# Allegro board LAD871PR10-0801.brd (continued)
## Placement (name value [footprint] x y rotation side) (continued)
PU1200  -  [NB681GD-Z_QFN13_2X3]  36.32 53.21 0 bottom
PU1400  SY8286RAC_QFN20_3X3  [SY8286RAC_QFN20_3X3-S]  130.93 138.81 180 bottom
PWR1  JXT_FP202DH-004M10M  [JXT_FP202DH-004M10M_4P]  197.15 167.84 0 top
Q1901  -  [2N7002K_SOT23-3]  165.5 64.77 90 top
Q2405  -  [2N7002K_SOT23-3]  53.55 72.64 90 top
Q2505  -  [2N7002K_SOT23-3]  31.27 16.76 270 top
Q2601  -  [DMN66D0LDW-7_SOT363-6]  153.49 156.78 180 bottom
Q2603  -  [LMBT3904LT1G_SOT23-3]  53.02 64.11 180 bottom
Q3001  -  [2N7002K_SOT23-3]  61.93 169.55 180 top
Q3004  NTK3139PT1G_SOT723-3  [2N7002K_SOT23-3]  57.56 171.84 270 top
Q5401  LMBT3904LT1G-GP  [MMBT3904_SOT23-3]  27.59 78.99 270 top
Q5402  -  [DMN66D0LDW-7_SOT363-6]  33 78.25 90 bottom
Q5403  -  [2N7002K_SOT23-3]  28.99 73.98 270 top
Q6101  -  [DDTA144VCA-7-F_SOT23-3]  35.24 5.25 0 top
Q6102  -  [DDTA144VCA-7-F_SOT23-3]  31.3 5.82 0 top
Q6105  -  [2N7002K_SOT23-3]  44.27 12.37 180 top
Q6201  -  [DDTA144VCA-7-F_SOT23-3]  195.51 108.94 0 top
Q6202  -  [LN2306LT1G_SOT23-3]  188.42 126.68 90 top
Q6203  NTK3139PT1G_SOT723-3  [2N7002K_SOT23-3]  52.13 79.02 180 top
Q6204  -  [LN2306LT1G_SOT23-3]  55.4 70.48 270 top
Q6205  -  [LN2306LT1G_SOT23-3]  196.53 18.01 180 bottom
Q6206  -  [LN2306LT1G_SOT23-3]  195.64 106.45 180 top
Q6501  -  [DMN66D0LDW-7_SOT363-6]  45.44 72.8 0 top
QC2  -  [DMN66D0LDW-7_SOT363-6]  155.17 91.37 0 bottom
QC4  -  [DMN66D0LDW-7_SOT363-6]  35.76 11.36 180 top
QV1  DMN66D0LDW-7 2N SOT363-6  [2N7002KDWH_SOT363-6]  174.05 125.35 135 top
R437  4.7K_0402_5%  [R_0402]  141.09 159.52 270 top
R1902  10K_0402_5%  [R_0402]  163.52 67.31 180 top
R2405  0_0402_5%  [R_0402]  195.76 85.48 270 top
R2407  100K_0402_1%  [R_0402]  182.62 61.85 180 top
R2446  10K_0402_1%  [R_0402]  182.62 60.96 180 top
R2455  0_0402_5%  [R_0402]  181.79 85.93 270 top
R2502  1K_0402_5%  [R_0402]  32.52 14.35 180 top
R2504  10M_0402_5%  [R_0402]  33.38 14.35 0 top
R2603  18.7K_0402_1%  [R_0402]  159.82 158.62 90 bottom
R2604  2K_0402_1%  [R_0402]  158.24 167.72 270 bottom
R2605  0_0402_5%  [R_0402]  95.19 143.73 0 bottom
R2606  0_0402_5%  [R0402_0OHM]  96.93 140.17 180 bottom
R2608  6.98K_0402_1%  [R_0402]  121.9 99.86 270 bottom
R2609  24.9K_0402_1%  [R_0402]  122.79 99.86 270 bottom
R2610  100K +-1% NCP15WF104F03RC 0402  [R_0402]  121.79 94.49 0 top
R2611  0_0402_5%  [R0402_0OHM]  187.25 73.29 270 bottom
R2701  0_0402_5%  [R0402_0OHM]  177.27 20.45 0 top
R2702  0_0805_5%  [R0805_0OHM]  176.2 10.83 0 bottom
R2703  0_0603_5%  [R0603_0OHM]  192.65 19.69 0 bottom
R2704  0_0805_5%  [R0805_0OHM]  176.2 9.11 0 bottom
R2705  0_0402_5%  [R0402_0OHM]  189.11 7.56 180 bottom
R2706  0_0805_5%  [R0805_0OHM]  191.99 10.54 0 bottom
R2707  20K_0402_1%  [R_0402]  181.94 21.67 90 bottom
R2708  0_0402_5%  [R0402_0OHM]  177.4 13.21 0 top
R2709  200K_0402_1%  [R_0402]  180.8 21.67 90 bottom
R2711  100K_0402_5%  [R_0402]  190.15 19.52 180 bottom
R2712  0_0402_5%  [R0402_0OHM]  186.87 29.13 90 bottom
R2713  0_0402_5%  [R_0402]  185.92 29.13 90 bottom
R2714  0_0402_5%  [R0402_0OHM]  177.29 13.3 0 bottom
R2716  BLM15PX221SN1D_2P  [MURAT_BLM15PX221SN1D_2P]  177.29 14.19 0 bottom
R2717  10K_0402_5%  [R_0402]  178.24 25.45 90 bottom
R2718  33_0402_5%  [R_0402]  177.35 18.8 0 bottom
R2719  0_0402_5%  [R0402_0OHM]  177.1 15.52 0 bottom
R2720  0_0402_5%  [R0402_0OHM]  177.23 16.41 0 bottom
R2722  100K_0402_5%  [R_0402]  178.42 22.48 0 bottom
R2901  BLM15PD800SN1D_2P  [MURAT_BLM15PD800SN1D_2P]  90.56 5.08 0 top
R2902  BLM15PD800SN1D_2P  [MURAT_BLM15PD800SN1D_2P]  90.56 6.67 0 top
R2903  BLM15PD800SN1D_2P  [MURAT_BLM15PD800SN1D_2P]  90.56 8.64 0 top
R2904  BLM15PD800SN1D_2P  [MURAT_BLM15PD800SN1D_2P]  90.56 9.97 0 top
R2906  0_0603_5%  [R0603_0OHM]  185.37 22.13 180 top
R2907  0_0603_5%  [R0603_0OHM]  185.37 28.1 180 top
R2908  10_0402_1%  [R_0402]  188.85 15.27 0 bottom
R2909  0_0603_5%  [R0603_0OHM]  185.37 26.7 180 top
R2910  10_0402_1%  [R_0402]  191.88 15.75 0 bottom
R2911  0_0603_5%  [R0603_0OHM]  185.37 23.53 180 top
R2912  4.7K_0402_5%  [R_0402]  189.74 16.16 0 bottom
R2913  4.7K_0402_5%  [R_0402]  191.88 17.4 0 bottom
R2919  10K_0402_5%  [R_0402]  186.49 27.99 90 top
R2920  10K_0402_5%  [R_0402]  186.49 26.87 270 top
R2921  1K_0402_5%  [R_0402]  191.12 24.38 0 bottom
R2922  1K_0402_5%  [R_0402]  191.12 23.11 0 bottom
R2923  0_0603_5%  [R0603_0OHM]  180.8 24.92 270 bottom
R3001  0_0603_5%  [R_0603]  54.56 174.21 90 top
R3005  0_0402_5%  [R0402_0OHM]  53.14 162.05 0 top
R3006  0_0603_5%  [R0603_0OHM]  55.77 172.94 180 top
R3015  15K_0402_5%  [R_0402]  53.91 167.61 0 top
R3016  0_0402_5%  [R0402_0OHM]  56.72 163.88 270 top
R3021  10K_0402_5%  [R_0402]  62.43 173.33 270 top
R3022  20K_0402_5%  [R_0402]  62.38 171.48 180 top
R3023  100K_0402_5%  [R_0402]  63.39 170.45 90 top
R3032  2.49K_0402_1%  [R_0402]  44.43 173.42 0 top
R3101  75_0603_5%  [R_0603]  16.31 169.67 270 top
R3102  75_0603_5%  [R_0603]  16.31 169.67 270 bottom
R3103  75_0603_5%  [R_0603]  16.31 171.07 90 bottom
R3104  75_0603_5%  [R_0603]  16.31 171.07 90 top
R3201  33_0402_5%  [R_0402]  20.68 17.91 90 bottom
R3202  0_0402_5%  [R0402_0OHM]  15.3 21.29 270 bottom
R3203  6.2K_0402_1%  [R_0402]  14.37 12.93 270 bottom
R3204  0_0402_5%  [R_0402]  12.44 11.57 90 bottom
R3205  0_0402_5%  [R_0402]  11.55 11.57 90 bottom
R3301  0_0402_5%  [R0402_0OHM]  30.1 23.08 180 top
R3501  0_0402_5%  [R0402_0OHM]  134.67 98.99 45 bottom
R5201  0_0402_5%  [R0402_0OHM]  93.53 160.91 270 bottom
R5202  100K_0402_5%  [R_0402]  82.35 154.1 180 bottom
R5203  0_0402_5%  [R_0402]  99.04 158.67 270 bottom
R5204  0_0402_5%  [R_0402]  99.93 158.67 270 bottom
R5205  33_0402_5%  [R_0402]  100.86 158.55 270 bottom
R5206  0_0402_5%  [R0402_0OHM]  65.33 164.67 270 top
R5207  33_0402_5%  [R_0402]  94.04 158.11 90 bottom
R5208  10K_0402_5%  [R_0402]  104.63 171.2 0 bottom
R5209  0_0402_5%  [R_0402]  105.54 172.08 180 bottom
R5210  100_0402_5%  [R_0402]  104.63 170.31 0 bottom
R5211  0_0805_5%  [R_0805]  80.32 157.57 270 bottom
R5212  0_0402_5%  [R_0402]  100.86 162.11 270 bottom
R5213  0_0402_5%  [R0402_0OHM]  84.44 159.77 0 bottom
R5214  0_0805_5%  [R_0805]  74.64 164.97 0 bottom
R5218  100K_0402_5%  [R_0402]  87.22 159.68 180 bottom
R5219  100K_0402_5%  [R_0402]  88.09 159.68 0 bottom
R5222  0_0402_5%  [R_0402]  64.45 164.67 270 top
R5229  0_0603_5%  [R_0603]  97.99 155.8 90 bottom
R5230  0_0603_5%  [R0603_0OHM]  89.15 151.26 0 bottom
R5231  0_0603_5%  [R_0603]  89.15 152.53 0 bottom
R5232  0_0603_5%  [R_0603]  95.5 150.69 180 bottom
R5401  5.6_0402_1%  [R_0402]  21.34 77.86 180 bottom
R5402  5.6_0402_1%  [R_0402]  21.34 76.97 180 bottom
R5403  5.6_0402_1%  [R_0402]  21.48 75.89 180 bottom
R5404  5.6_0402_1%  [R_0402]  21.48 75 180 bottom
R5405  5.6_0402_1%  [R_0402]  20.45 68.9 270 bottom
R5406  5.6_0402_1%  [R_0402]  21.34 68.9 270 bottom
R5407  5.6_0402_1%  [R_0402]  21.46 73.97 180 bottom
R5408  5.6_0402_1%  [R_0402]  21.46 73.08 180 bottom
R5410  200K_0402_1%  [R_0402]  17.1 79.14 90 bottom
R5411  150K_0402_5%  [R_0402]  17.97 79.15 0 bottom
R5412  10K_0402_5%  [R_0402]  31.49 79.36 90 top
R5413  100K_0402_5%  [R_0402]  34.48 70.45 0 bottom
R5414  150_0402_5%  [R_0402]  18.94 77.89 270 bottom
R5415  150_0402_5%  [R_0402]  20.39 66.39 0 bottom
R5416  150_0402_5%  [R_0402]  18.94 75.93 270 bottom
R5417  150_0402_5%  [R_0402]  18.94 73.96 270 bottom
R5418  0_0402_5%  [R_0402]  27.17 74.56 270 top
R5419  0_0402_5%  [R_0402]  31.49 77.52 90 top
R5501  75_0402_1%  [R_0402]  24.08 64.37 270 top
R5502  4.7K_0402_5%  [R_0402]  28.72 59.54 270 bottom
R5503  0_0603_5%  [R0603_0OHM]  23.13 67.4 0 top
R5504  0_0603_5%  [R0603_0OHM]  30.3 59.02 0 top
R5505  12K_0402_1%  [R_0402]  31.7 64.28 90 bottom
R5507  33_0402_5%  [R_0402]  26.81 68.41 90 top
R5508  4.7K_0402_5%  [R_0402]  29.99 61.76 270 bottom
R5509  4.7K_0402_5%  [R_0402]  29.99 59.54 270 bottom
R5510  100K_0402_5%  [R_0402]  31.51 68.09 90 top
R5511  33_0402_5%  [R_0402]  25.92 68.41 90 top
R5512  4.7K_0402_5%  [R_0402]  29.1 61.76 270 bottom
R5513  75_0402_1%  [R_0402]  24.08 62.08 270 top
R5514  75_0402_1%  [R_0402]  24.08 59.42 270 top
R5515  4.7K_0402_5%  [R_0402]  30.88 59.54 270 bottom
R5516  4.7K_0402_5%  [R_0402]  30.88 61.76 270 bottom
R5517  0_0402_5%  [R_0402]  32.4 68.09 90 top
R5601  0_0805_5%  [R0805_0OHM]  192.04 39.81 270 bottom
R5602  0_0402_5%  [R_0402]  153.8 82.36 180 top
R5603  0_0805_5%  [R_0805]  176.14 43.21 270 top
R5604  10K_0402_5%  [R_0402]  152.79 80.39 180 top
R5605  0_0402_5%  [R0402_0OHM]  186.62 35.81 180 bottom
R5607  100K_0402_5%  [R_0402]  181.59 44.45 0 top
R5801  0_0402_5%  [R_0402]  160.47 63.11 90 bottom
R5802  0_0402_5%  [R_0402]  161.36 63.11 90 bottom
R5803  0_0402_5%  [R0402_0OHM]  160.79 49.28 180 bottom
R5804  0_0402_5%  [R_0402]  170.41 49.72 0 top
R5805  0_0402_5%  [R0402_0OHM]  168.4 51.7 270 top
R5806  0_0402_5%  [R_0402]  170.29 52.2 0 top
R5807  0_0402_5%  [R0402_0OHM]  170.41 50.8 0 top
R5808  0_0402_5%  [R0402_0OHM]  159.06 55.42 90 bottom
R5809  0_0805_5%  [R0805_0OHM]  163.7 36.36 90 bottom
R5810  0_0402_5%  [R_0402]  172.71 40.25 90 bottom
R5811  0_0402_5%  [R0402_0OHM]  159.95 55.42 90 bottom
R5812  0_0402_5%  [R0402_0OHM]  170.29 53.21 0 top
R6102  100_0402_5%  [R_0402]  191.12 173.23 0 top
R6103  470R2J-2-GP  [R_0402]  30.99 3.78 0 top
R6107  390R2J-3-GP  [R_0402]  27.87 5.79 270 top
R6109  100_0402_5%  [R_0402]  191.91 175.98 90 top
R6110  10K_0402_5%  [R_0402]  40.9 10.32 0 top
R6201  1K_0402_5%  [R_0402]  195.33 113.03 180 top
R6202  100K_0402_5%  [R_0402]  194.16 100.9 0 top
R6203  10K_0402_5%  [R_0402]  60.71 74.8 180 top
R6206  51K_0402_5%  [R_0402]  186.96 123.21 90 top
R6207  100K_0402_5%  [R_0402]  186.07 123.21 90 top
R6209  4.7K_0402_5%  [R_0402]  59.75 72.09 270 top
R6211  100_0603_1%  [R_0603]  55.49 73.53 0 top
R6212  0_0603_5%  [R_0603]  56.13 78.87 180 top
R6215  0_0402_5%  [R_0402]  54.6 75.17 90 top
R6301  0_0402_5%  [R_0402]  187.56 36.45 0 top
R6302  0_0402_5%  [R_0402]  187.77 31.08 0 top
R6305  0_0603_5%  [R_0603]  192.14 12.06 0 bottom
R6505  100K_0402_5%  [R_0402]  59.8 77.47 0 top
R6506  2.2K_0402_5%  [R_0402]  59.8 73.91 0 top
R6507  10K_0402_5%  [R_0402]  82.66 159.77 0 bottom
R6508  2.2K_0402_5%  [R_0402]  59.8 73.02 0 top
R6510  4.7K_0402_5%  [R_0402]  144.01 159.52 270 top
R6511  0_0402_5%  [R0402_0OHM]  188.33 9 90 bottom
R6512  100K_0402_5%  [R_0402]  177.4 14.1 0 top
R6514  0_0402_5%  [R_0402]  177.48 20.88 90 bottom
R6515  0_0402_5%  [R0402_0OHM]  177.35 19.94 0 bottom
R6516  0_0402_5%  [R0402_0OHM]  179.33 22.61 180 top
R6517  100K_0402_5%  [R_0402]  173.08 53.21 0 top
R6518  1K_0402_5%  [R_0402]  54.83 168.5 180 top
R6519  20K_0402_1%  [R_0402]  48.37 78.49 0 top
R6520  0_0402_5%  [R_0402]  191.95 65.4 0 top
R6522  33_0402_5%  [R_0402]  29.25 19.43 0 top
R6523  0_0402_5%  [R_0402]  187.38 60.12 90 top
R6524  0_0402_5%  [R0402_0OHM]  186.48 61.91 0 top
R6525  0_0805_5%  [R0805_0OHM]  76.7 168.49 270 bottom
RC1  100K_0402_5%  [R_0402]  126.5 106.24 180 top
RC2  24.9_0402_1%  [R_0402]  112.08 92.2 180 top
RC3  100_0402_1%  [R_0402]  133.21 95.69 45 top
RC4  200_0402_1%  [R_0402]  140.82 78.87 0 bottom
RC5  121_0402_1%  [R_0402]  126.49 74.69 270 top
RC6  80.6_0402_1%  [R_0402]  127.37 74.69 270 top
RC7  100_0402_1%  [R_0402]  128.33 74.69 270 top
RC9  1K_0402_5%  [R_0402]  156.01 71.5 90 bottom
RC12  1K_0402_5%  [R_0402]  153.09 88.15 270 bottom
RC13  10K_0402_5%  [R_0402]  158.63 65.72 180 bottom
RC14  1K_0402_5%  [R_0402]  152.2 88.15 270 bottom
RC15  1K_0402_5%  [R_0402]  144.17 89.24 0 bottom
RC17  1K_0402_5%  [R_0402]  144.17 90.13 0 bottom
RC18  22_0402_5%  [R_0402]  151.94 70.42 0 bottom
RC19  1K_0402_5%  [R_0402]  144.05 85.69 0 bottom
RC20  1K_0402_5%  [R_0402]  144.05 86.58 0 bottom
RC21  10K_0402_1%  [R_0402]  156.76 67.12 0 top
RC22  22_0402_5%  [R_0402]  151.95 71.31 0 bottom
RC23  8.2K_0402_5%  [R_0402]  144.17 86.96 0 top
RC25  10K_0402_5%  [R_0402]  144.05 87.47 0 bottom
RC27  8.2K_0402_5%  [R_0402]  139.12 68.71 0 bottom
RC29  33_0402_5%  [R_0402]  158.17 73.43 180 bottom
RC30  1K_0402_5%  [R_0402]  150.31 73.91 180 bottom
RC31  1K_0402_5%  [R_0402]  155.06 77.48 180 bottom
RC35  51_0402_1%  [R_0402]  104.18 101.61 90 bottom
RC37  0_0402_5%  [R0402_0OHM]  159.95 79.88 270 bottom
RC43  0_0402_5%  [R_0402]  92.97 100.2 180 bottom
RC44  113_0402_1%  [R_0402]  142.61 84.51 90 top
RC45  100_0402_1%  [R_0402]  135.8 92.79 45 top
RC46  1M_0402_1%  [R_0402]  125.04 104.84 180 bottom
RC47  10K_0402_5%  [R_0402]  153.17 76.33 180 top
RC48  1K_0402_5%  [R_0402]  167.51 51.7 270 top
RC50  10K_0402_5%  [R_0402]  153.17 75.44 180 top
RC52  2.7K_0402_1%  [R_0402]  125.41 89.19 90 top
RC54  10M_0402_5%  [R_0402]  145.1 81.34 180 bottom
RC56  20K_0402_5%  [R_0402]  142.03 64.87 270 top
RC57  20K_0402_5%  [R_0402]  144.44 64.81 270 top
RC62  49.9K_0402_1%  [R_0402]  144.89 83.76 0 bottom
RC63  49.9K_0402_1%  [R_0402]  151.31 85.05 90 bottom
RC65  100K_0402_5%  [R_0402]  149.73 80.28 270 top
RC68  10K_0402_5%  [R_0402]  155.11 55.63 0 bottom
RC69  330K_0402_5%  [R_0402]  142.91 64.87 270 top
RC70  10K_0402_5%  [R_0402]  155.58 70.42 180 top
RC71  1K_0402_5%  [R_0402]  97.07 103.06 0 bottom
RC72  8.2K_0402_5%  [R_0402]  146.22 64.81 270 top
RC73  10K_0402_5%  [R_0402]  145.71 81.98 360 top
RC74  10K_0402_5%  [R_0402]  152.47 70.99 180 top
RC75  10K_0402_5%  [R_0402]  151.56 55.63 0 bottom
RC76  0_0402_5%  [R_0402]  174.61 69.85 0 bottom
RC78  60.4_0402_1%  [R_0402]  97.07 101.64 270 bottom
RC79  49.9_0402_1%  [R_0402]  102.66 102.53 270 bottom
RC80  1K_0402_5%  [R_0402]  101.77 102.53 270 bottom
RC83  1K_0402_5%  [R_0402]  96.2 104.22 270 bottom
RC84  499_0402_1%  [R_0402]  96.18 101.64 270 bottom
RC88  49.9_0402_1%  [R_0402]  129.22 74.69 270 top
RC89  49.9_0402_1%  [R_0402]  130.1 74.69 270 top
RC90  49.9_0402_1%  [R_0402]  98.73 92.93 180 top
RC91  49.9_0402_1%  [R_0402]  98.73 92.04 180 top
RC92  33_0402_5%  [R_0402]  152.47 53.85 180 bottom
RC93  33_0402_5%  [R_0402]  152.47 50.29 180 bottom
RC94  33_0402_5%  [R_0402]  152.47 52.07 180 bottom
RC95  33_0402_5%  [R_0402]  152.47 49.4 180 bottom
RC96  200_0402_1%  [R_0402]  143.5 84.51 90 top
RC109  10K_0402_1%  [R_0402]  92.77 95.76 0 bottom
RC110  10K_0402_1%  [R_0402]  94.74 101.61 270 bottom
RC112  10K_0402_1%  [R_0402]  91.75 97.28 90 bottom
RC113  10K_0402_1%  [R_0402]  95.31 104.22 270 bottom
RC114  49.9_0402_1%  [R_0402]  98.66 103.88 90 top
RC115  1.5K_0402_5%  [R_0402]  134.15 101.04 90 bottom
RC120  100K_0402_5%  [R_0402]  97.96 100.72 90 bottom
RC124  100K_0402_5%  [R_0402]  77.27 66.92 90 bottom
RC140  100_0402_1%  [R_0402]  120.98 99.05 180 bottom
RC141  100_0402_1%  [R_0402]  119.2 99.05 180 bottom
RC152  56_0402_1%  [R_0402]  99.93 103.42 270 bottom
RC153  220_0402_5%  [R_0402]  99.93 100.72 90 bottom
RC157  100_0402_1%  [R_0402]  98.85 101.64 270 bottom
RC158  1K_0402_5%  [R_0402]  153.33 55.63 0 bottom
RC161  100_0402_1%  [R_0402]  95.54 92.69 270 bottom
RC163  100_0402_1%  [R_0402]  94.92 90.79 180 bottom
RC166  100_0402_1%  [R_0402]  126.55 104.38 90 top
RC168  100_0402_1%  [R_0402]  124.49 91.47 0 top
RC169  0_0603_5%  [R0603_0OHM]  140.46 105.09 180 top
RC170  0_0603_5%  [R0603_0OHM]  133.22 105.03 0 bottom
RC171  0_0603_5%  [R0603_0OHM]  134.04 105.09 180 top
RC172  0_0603_5%  [R0603_0OHM]  146.11 97.09 180 top
RC173  0_0603_5%  [R0603_0OHM]  135.06 105.09 0 top
RC175  2.2K_0402_5%  [R_0402]  33 77.09 0 bottom
RC178  2.2K_0402_5%  [R_0402]  32.14 77.09 180 bottom
RC181  100K_0402_5%  [R_0402]  36.12 64.08 270 top
RC182  100K_0402_5%  [R_0402]  36.12 61.39 90 top
RC183  8.2K_0402_5%  [R_0402]  149.39 76.79 180 top
RC186  4.7K_0402_5%  [R_0402]  149.39 77.68 180 top
RC187  4.7K_0402_5%  [R_0402]  152.47 51.18 180 bottom
RC189  10K_0402_5%  [R_0402]  153.17 74.55 180 top
RC213  0_0603_5%  [R0603_0OHM]  150.42 77.91 270 top
RC214  0_0603_5%  [R0603_0OHM]  151.12 88.26 270 bottom
RC216  0_0402_5%  [R0402_0OHM]  152.47 54.74 180 bottom
RC220  1M_0402_5%  [R_0402]  160.64 54.42 0 top
RC223  1K_0402_5%  [R_0402]  152.47 52.96 180 bottom
RC237  10K_0402_5%  [R_0402]  145.52 102.12 90 bottom
RC238  0_0603_5%  [R_0603]  128.07 105.79 0 top
RC239  10K_0402_5%  [R_0402]  145.29 91.08 180 bottom
RC243  300K_0402_5%  [R_0402]  144.6 60.13 180 top
RC245  10K_0402_5%  [R_0402]  140.04 67.82 180 bottom
RC246  10K_0402_5%  [R_0402]  141.66 96.79 270 bottom
RC248  10K_0402_5%  [R_0402]  144.63 102.12 90 bottom
RC267  10K_0402_5%  [R_0402]  145.29 92.01 180 bottom
RC268  10K_0402_5%  [R_0402]  141.77 91.01 90 bottom
RC272  10K_0402_5%  [R_0402]  148.77 65.11 180 top
RC277  10K_0402_5%  [R_0402]  141.66 101.56 180 bottom
RC288  10K_0402_5%  [R_0402]  151.56 70.1 0 top
RC291  10K_0402_5%  [R_0402]  141.73 99.33 270 bottom
RC292  10K_0402_5%  [R_0402]  149.28 85.88 180 bottom
RC293  10K_0402_5%  [R_0402]  147.76 91.26 270 bottom
RC309  0_0603_5%  [R0603_0OHM]  140.46 103.89 180 top
RC310  0_0603_5%  [R0603_0OHM]  140.46 106.3 180 top
RC312  100K_0402_5%  [R_0402]  149.14 89.6 0 top
RC317  33_0402_5%  [R_0402]  141.84 75.95 0 bottom
RC318  33_0402_5%  [R_0402]  146.23 77.14 0 bottom
RC319  33_0402_5%  [R_0402]  141.59 77.41 0 bottom
RC320  33_0402_5%  [R_0402]  148.01 77.14 0 bottom
RC327  33_0402_5%  [R_0402]  149.4 74.82 0 bottom
RC329  15_0402_1%  [R_0402]  162.74 79.5 270 bottom
RC330  15_0402_1%  [R_0402]  161.73 78.61 90 bottom
RC331  15_0402_1%  [R_0402]  158.17 71.67 180 bottom
RC332  15_0402_1%  [R_0402]  158.17 72.56 180 bottom
RC333  15_0402_1%  [R_0402]  157.99 75.22 180 bottom
RC339  4.7K_0402_5%  [R_0402]  159.95 81.66 270 bottom
RC340  100_0402_1%  [R_0402]  104.58 80.63 90 top
RC341  100_0402_1%  [R_0402]  105.46 81.7 270 top
RC345  0_0402_5%  [R0402_0OHM]  161.28 71.55 90 top
RC347  0_0402_5%  [R_0402]  155.84 72.34 180 top
RC348  51_0402_5%  [R_0402]  105.51 101.61 90 bottom
RC349  51_0402_5%  [R_0402]  102.27 101.04 90 top
RC350  51_0402_5%  [R_0402]  104.05 101.04 90 top
RC351  51_0402_5%  [R_0402]  103.16 101.04 90 top
RC352  0_0603_5%  [R_0603]  133.47 103.38 0 bottom
RC353  1K_0402_5%  [R_0402]  135.82 101.99 270 bottom
RC354  1K_0402_1%  [R_0402]  145.98 76.2 180 bottom
RC355  1K_0402_1%  [R_0402]  153.36 74.38 90 bottom
RC356  10K_0402_5%  [R_0402]  145.29 94.68 180 bottom
RC358  150K_0402_5%  [R_0402]  148.65 90.35 90 bottom
RC359  10K_0402_5%  [R_0402]  183.46 118.24 180 bottom
RC360  10K_0402_5%  [R_0402]  141.26 102.5 90 bottom
RC361  0_0402_5%  [R_0402]  141.48 85.47 135 top
RC364  0_0603_5%  [R0603_0OHM]  153.75 143.92 45 top
RC365  150K_0402_5%  [R_0402]  155 79.25 90 bottom
RC366  1K_0402_5%  [R_0402]  141.61 83.26 180 bottom
RC368  0_0603_5%  [R0603_0OHM]  146.11 98.42 180 top
RC369  8.2K_0402_5%  [R_0402]  139.76 66.93 0 bottom
RC374  10K_0402_5%  [R_0402]  148.22 87.5 180 top
RC375  10K_0402_5%  [R_0402]  147.06 89.78 90 top
RC376  10K_0402_5%  [R_0402]  154.88 68.58 180 top
RC377  10K_0402_5%  [R_0402]  153.97 67.69 0 top
RC378  10K_0402_5%  [R_0402]  151.11 82.36 0 top
RC379  10K_0402_5%  [R_0402]  153.17 73.66 180 top
RC380  10K_0402_5%  [R_0402]  152.79 81.34 180 top
RC381  10K_0402_5%  [R_0402]  152.25 72.77 0 top
RC382  49.9K_0402_1%  [R_0402]  148.36 84.99 0 bottom
RC383  10K_0402_5%  [R_0402]  140.81 89.88 0 bottom
RC384  10K_0402_5%  [R_0402]  144.17 87.85 0 top
RC385  0_0402_5%  [R0402_0OHM]  150.06 91.38 180 top
RC386  0_0402_5%  [R_0402]  150.06 90.49 180 top
RC387  10K_0402_5%  [R_0402]  152.2 85.08 90 bottom
RC388  1K_0402_5%  [R_0402]  160.39 71.55 90 top
RC390  100K_0402_5%  [R_0402]  150.42 79.88 270 bottom
RC391  0_0402_5%  [R_0402]  155.58 69.53 180 top
RC392  0_0402_5%  [R0402_0OHM]  162.17 72.47 270 top
RC393  1K_0402_5%  [R_0402]  144.39 84.51 90 top
RC394  0_0402_5%  [R_0402]  139.87 101.58 270 bottom
RC395  0_0402_5%  [R0402_0OHM]  155.84 71.45 180 top
RC396  0_0603_5%  [R_0603]  148.84 84.45 90 top
RC1102  100K_0402_5%  [R_0402]  143.68 61.09 0 top
RC1103  10K_0402_1%  [R_0402]  167.2 92.1 270 top
RC1104  0_0402_5%  [R_0402]  93.85 101.1 270 bottom
RC1105  0_0402_5%  [R_0402]  152.47 74.38 90 bottom
RC1106  0_0402_5%  [R0402_0OHM]  162.11 69.39 90 top
RC1107  0_0402_5%  [R_0402]  174.69 66.36 180 top
RD1  0_0402_5%  [R_0402]  153 33.21 180 bottom
RD2  0_0402_5%  [R_0402]  153 32.33 180 bottom
RD3  0_0402_5%  [R_0402]  121.79 27.99 90 top
RD4  0_0402_5%  [R_0402]  161.42 21.65 180 bottom
RD5  0_0402_5%  [R0402_0OHM]  161.42 20.76 180 bottom
RD6  0_0402_5%  [R_0402]  130.49 13.51 90 top
RD7  240_0402_1%  [R_0402]  113.98 28.5 90 top
RD8  240_0402_1%  [R_0402]  119.94 15.99 90 top
RD28  0_0402_5%  [R0402_0OHM]  152.08 34.1 0 bottom
RD29  0_0402_5%  [R0402_0OHM]  152.08 31.44 0 bottom
RD30  0_0402_5%  [R0402_0OHM]  120.2 30.02 90 top
RD31  0_0402_5%  [R_0402]  113.66 15.93 90 top
RD35  470_0402_1%  [R_0402]  114.8 15.93 90 top
RD38  0_0402_5%  [R0402_0OHM]  160.51 22.54 0 bottom
RD39  0_0402_5%  [R_0402]  160.51 19.88 0 bottom
RD40  0_0402_5%  [R0402_0OHM]  129.53 14.43 270 top
RE25  100K_0402_5%  [R_0402]  185.35 85.93 270 top
RE26  0_0402_5%  [R0402_0OHM]  186.24 85.93 270 top
RE31  100K_0402_5%  [R_0402]  189.85 66.8 0 bottom
RE32  2.2K_0402_5%  [R_0402]  158.31 158.62 180 bottom
RE33  1KR2J-1-GP  [R_0402]  177.27 24.51 0 bottom
RE35  2.2K_0402_5%  [R_0402]  181.1 22.32 0 top
RE36  2.2K_0402_5%  [R_0402]  181.1 23.21 0 top
RE39  0_0402_5%  [R_0402]  38.84 75.82 0 bottom
RE40  0_0402_5%  [R_0402]  38.84 74.93 0 bottom
RE41  0_0402_5%  [R_0402]  38.84 73.91 0 bottom
RE42  0_0402_5%  [R_0402]  38.84 72.9 0 bottom
RE43  2.2K_0402_5%  [R_0402]  36.21 78.99 0 bottom
RE44  2.2K_0402_5%  [R_0402]  36.21 78.1 0 bottom
RE45  2.2K_0402_5%  [R_0402]  28.46 69.93 90 top
RE46  2.2K_0402_5%  [R_0402]  29.35 69.93 90 top
RE71  49.9_0402_1%  [R_0402]  186.14 90.02 0 bottom
RE72  10K_0402_5%  [R_0402]  188.19 85.22 0 bottom
RE73  10K_0402_5%  [R_0402]  188.32 82.49 0 bottom
RE74  10K_0402_5%  [R_0402]  188.32 83.44 0 bottom
RE75  100K_0402_5%  [R_0402]  188.19 84.33 0 bottom
RE343  0_0603_5%  [R0603_0OHM]  176.65 74.29 90 bottom
RE345  100K_0402_1%  [R_0402]  185.6 61.01 90 top
RE347  100K_0402_1%  [R_0402]  184.71 61.01 90 top
RE348  0_0402_5%  [R0402_0OHM]  184.46 85.01 90 top
RE349  0_0603_5%  [R0603_0OHM]  188.78 66.87 90 bottom
RE353  43_0402_1%  [R_0402]  174.99 68.81 180 top
RE354  10K_0402_5%  [R_0402]  182.68 66.85 90 bottom
RE355  10K_0402_5%  [R_0402]  177.93 71.88 180 bottom
RE356  1K_0402_5%  [R_0402]  188.27 64.85 270 top
RE357  1K_0402_5%  [R_0402]  174.58 75.25 180 top
RE358  100K_0402_5%  [R_0402]  189.16 61.93 270 top
RE366  0_0402_5%  [R0402_0OHM]  190.18 64.85 270 top
RE367  10K_0402_5%  [R_0402]  178.12 77.09 180 bottom
RE380  100K_0402_5%  [R_0402]  179.63 74.75 270 bottom
RE385  10K_0402_5%  [R_0402]  187.25 64.85 270 top
RE388  100K_0402_5%  [R_0402]  190.57 72.2 180 bottom
RE389  100K_0402_5%  [R_0402]  174.89 79.63 180 top
RE392  100K_0402_5%  [R_0402]  189.62 75.31 180 bottom
RE394  0_0402_5%  [R0402_0OHM]  189.62 74.42 180 bottom
RE396  10K_0402_1%  [R_0402]  187.95 76.25 90 bottom
RE397  10K_0402_1%  [R_0402]  188.84 77.17 270 bottom
RE398  0_0603_5%  [R0603_0OHM]  184.97 66.99 90 bottom
RE399  300_0402_5%  [R_0402]  184.26 64.24 270 top
RE400  300_0402_5%  [R_0402]  187.38 59.19 270 top
RE404  100K_0402_5%  [R_0402]  177.79 74.43 270 bottom
RE408  100K_0402_5%  [R_0402]  195.69 66.67 0 top
RE409  100K_0402_5%  [R_0402]  181.84 69.85 0 bottom
RE410  0_0402_5%  [R0402_0OHM]  195.5 79.57 0 top
RE413  15_0402_1%  [R_0402]  195.76 83.45 270 top
RE414  15_0402_1%  [R_0402]  196.41 80.45 180 top
RE416  15_0402_1%  [R_0402]  196.41 81.34 180 top
RE420  0_0402_5%  [R0402_0OHM]  186.14 89.13 0 bottom
RE421  0_0402_5%  [R0402_0OHM]  188.39 89.17 0 bottom
RE422  0_0402_5%  [R0402_0OHM]  188.39 88.28 0 bottom
RE423  0_0402_5%  [R0402_0OHM]  187.74 86.68 0 bottom
RE424  4.7K_0402_5%  [R_0402]  196.26 70.99 0 top
RE425  4.7K_0402_5%  [R_0402]  196.26 71.88 0 top
RE426  2.2K_0402_5%  [R_0402]  196.26 72.77 0 top
RE427  2.2K_0402_5%  [R_0402]  196.26 73.66 0 top
RE428  10K_0402_5%  [R_0402]  192.59 69.58 90 bottom
RE432  2.2K_0402_5%  [R_0402]  155.62 158.62 0 bottom
RE433  0_0402_5%  [R0402_0OHM]  188.27 61.01 90 top
RE434  0_0402_5%  [R0402_0OHM]  180.9 66.85 90 bottom
RE437  100K_0402_5%  [R_0402]  190.76 67.69 180 bottom
RE438  0_0402_5%  [R0402_0OHM]  182.05 80.14 90 bottom
RE439  10K_0402_5%  [R_0402]  140.74 100.67 0 bottom
RE440  100K_0402_5%  [R_0402]  187.94 78.04 0 bottom
RE441  10K_0402_5%  [R_0402]  189.08 88.65 0 top
RE442  0_0402_5%  [R_0402]  186.24 66.85 90 bottom
RE443  0_0402_5%  [R0402_0OHM]  186.49 60.12 90 top
RH206  1K_0402_1%~D  [R_0402]  124.9 31.51 270 top
RH207  1K_0402_1%~D  [R_0402]  128.52 15.99 90 top
RH209  1K_0402_1%~D  [R_0402]  125.85 30.59 90 top
RH210  1K_0402_1%~D  [R_0402]  130.42 15.99 90 top
RH211  24.9_0402_1%  [R_0402]  122.1 30.59 90 top
RH212  24.9_0402_1%  [R_0402]  76.63 60.26 0 bottom
RH484  2_0402_1%  [R_0402]  123.93 31.51 270 top
RH485  2_0402_1%  [R_0402]  131.5 15.99 90 top
RJ45  SANTA_130456-661  [SANTA_130456-661_8P]  11.78 167.4 90 bottom
RN19  2.2K_0402_5%  [R_0402]  155.62 88.46 0 bottom
RN20  2.2K_0402_5%  [R_0402]  154.04 89.78 90 bottom
RN5201  100_0804_8P4R_5%  [RP_0804_8P4R]  87.17 159.07 270 top
RN5203  100K_0804_8P4R_5%  [RP_0804_8P4R]  85.67 154.49 90 top
RN5402  470_0804_8P4R_5%  [RP_0804_8P4R]  25.29 71.92 180 top
RN5403  470_0804_8P4R_5%  [RP_0804_8P4R]  25.29 75.73 180 top
RP34  10K_8P4R_5%  [RP_0804_8P4R]  180.06 124.33 135 bottom
RPC3  10K_8P4R_5%  [RP_0804_8P4R]  138.65 100.99 90 bottom
RPE2  10K_8P4R_5%  [RP_0804_8P4R]  190.62 70.98 180 bottom
RPE3  10K_8P4R_5%  [RP_0804_8P4R]  182.04 64.33 270 top
RPE4  100K_8P4R_5%  [RP_0804_8P4R]  196.72 74.94 180 top
RPE5  100K_8P4R_5%  [RP_0804_8P4R]  191.81 86.69 270 top
RPE6  100K_8P4R_5%  [RP_0804_8P4R]  173.24 78.19 0 top
RPE7  100K_8P4R_5%  [RP_0804_8P4R]  173.24 72.84 0 top
RTC1  LOTES_AAA-BAT-054-K01  [LOTES_AAA-BAT-054-K01_2P]  27.15 14.61 180 bottom
RV1  1.69K_0402_1%  [R_0402]  156.39 136.78 135 top
RV2  1K_0402_1%  [R_0402]  166.3 131.57 45 top
RV3  1K_0402_1%  [R_0402]  155.63 136.02 135 top
RV4  100K_0402_5%  [R_0402]  146.55 130.24 315 bottom
RV5  45.3K_0402_1%  [R_0402]  173.79 122.58 270 top
RV6  45.3K_0402_1%  [R_0402]  171.38 127.38 315 top
RV8  8.45K_0402_1%  [R_0402]  155.89 129.41 135 top
RV9  2K_0402_1%  [R_0402]  155.89 130.68 315 top
RV11  8.45K_0402_1%  [R_0402]  152.96 129.79 315 top
RV12  2K_0402_1%  [R_0402]  154.23 129.79 135 top
RV13  4.75K_0402_1%  [R_0402]  154.87 127.89 135 top
RV15  8.45K_0402_1%  [R_0402]  150.3 131.32 45 top
RV16  4.75K_0402_1%  [R_0402]  151.82 131.57 225 top
RV17  1K_0402_1%  [R_0402]  175.06 128.65 135 top
RV20  1M_0402_5%  [R_0402]  144.9 131.19 270 bottom
RV21  10K_0402_5%  [R_0402]  172.9 124.08 135 bottom
RV27  0_0603_5%  [R0603_0OHM]  157.51 124.05 225 top
RV28  8.45K_0402_1%  [R_0402]  153.47 127.76 315 top
RV29  10K_0402_5%  [R_0402]  153.71 135.04 315 top
RV30  0_0603_5%  [R0603_0OHM]  159.03 123.8 225 top
RV31  0_0805_5%  [R0805_0OHM]  151.79 141.44 315 top
RV32  40.2_0402_1%  [R_0402]  154.37 148.4 315 bottom
RV33  40.2_0402_1%  [R_0402]  151.16 145.08 315 bottom
RV34  100_0402_1%  [R_0402]  152.45 145.1 135 bottom
RV35  100_0402_1%  [R_0402]  154.35 147.07 135 bottom
RV36  49.9_0402_1%  [R_0402]  182.81 128.78 270 top
RV37  10_0402_1%  [R_0402]  181.92 126.11 90 top
RV38  5.1K_0402_1%  [R_0402]  180.78 127 180 top
RV39  120_0402_1%  [R_0402]  159.06 144.4 315 top
RV40  51.1_0402_1%  [R_0402]  176.97 128.14 135 top
RV41  51.1_0402_1%  [R_0402]  175.7 127.89 225 top
RV43  40.2_0402_1%  [R_0402]  170.72 169.46 135 top
RV44  40.2_0402_1%  [R_0402]  171.35 170.09 135 top
RV58  4.7K_0402_5%  [R_0402]  183.19 124.59 0 top
RV59  10K_0402_5%  [R_0402]  154.29 135.96 315 top
RV66  40.2_0402_1%  [R_0402]  193.46 148.05 315 top
RV67  40.2_0402_1%  [R_0402]  194.09 148.68 315 top
RV71  0_0402_5%  [R0402_0OHM]  151.37 119.44 45 bottom
RV72  0_0402_5%  [R_0402]  152.65 119.45 225 bottom
RV77  0_0402_5%  [R_0402]  153.84 121.78 225 bottom
RV78  0_0402_5%  [R_0402]  156.9 119.06 45 bottom
RV81  4.7K_0402_5%  [R_0402]  170.24 122.68 315 bottom
RV82  4.7K_0402_5%  [R_0402]  170.87 123.32 315 bottom
RV83  16.2K_0402_1%  [R_0402]  169.6 122.05 315 bottom
RV84  10K_0402_5%  [R_0402]  155.88 119.34 225 bottom
RV87  10K_0402_5%  [R_0402]  155.32 120.08 225 bottom
RV88  10K_0402_5%  [R_0402]  154.04 120.07 45 bottom
RV89  10K_0402_5%  [R_0402]  157.16 120.65 225 bottom
RV90  1K_0402_1%  [R_0402]  169.47 129.41 225 top
RV91  10K_0402_5%  [R_0402]  170.14 128.63 315 top
RV110  4.99K_0402_1%  [R_0402]  174.62 173.35 135 top
RV112  4.99K_0402_1%  [R_0402]  169.16 167.63 135 bottom
RV139  4.99K_0402_1%  [R_0402]  174.68 174.69 315 top
RV142  4.99K_0402_1%  [R_0402]  194.04 148.72 315 bottom
RV143  4.99K_0402_1%  [R_0402]  191.5 146.12 315 top
RV144  4.99K_0402_1%  [R_0402]  167.88 167.65 315 bottom
RV146  4.7K_0402_5%  [R_0402]  174.86 123.32 0 top
RV149  4.99K_0402_1%  [R_0402]  195.33 148.71 135 bottom
RV150  4.99K_0402_1%  [R_0402]  191.52 144.84 135 top
RV151  10K_0402_5%  [R_0402]  175.19 126.49 135 bottom
RV152  10K_0402_5%  [R_0402]  173.92 126.49 315 bottom
RV153  0_0402_5%  [R_0402]  173.61 124.77 135 bottom
RV154  5.1K_0402_1%  [R_0402]  174.43 128.02 135 top
RV155  0_0402_5%  [R0402_0OHM]  155.19 122.88 225 bottom
RV156  0_0402_5%  [R0402_0OHM]  155.96 121.99 225 bottom
RV157  0_0402_5%  [R0402_0OHM]  156.59 121.35 225 bottom
RV158  0_0402_5%  [R0402_0OHM]  153.6 132.59 135 top
RV159  0_0402_5%  [R0402_0OHM]  154.23 133.22 135 top
RV160  10_0402_5%  [R_0402]  152.2 133.86 225 top
RV161  10_0402_5%  [R_0402]  151.95 135.64 135 top
RV162  4.7K_0402_5%  [R_0402]  148.07 127.57 45 bottom
RV163  4.7K_0402_5%  [R_0402]  148.08 128.85 225 bottom
RV164  0_0402_5%  [R_0402]  175.77 124.21 180 top
RV165  0_0402_5%  [R_0402]  175.9 121.67 180 top
RV260  10K_0402_5%  [R_0402]  187.97 124.33 180 bottom
RV261  243_0402_1%  [R_0402]  180.33 161.92 45 bottom
RV262  243_0402_1%  [R_0402]  173.29 172.08 135 top
RV263  243_0402_1%  [R_0402]  193.41 148.09 315 bottom
RV264  243_0402_1%  [R_0402]  185.41 157.22 45 top
RZ18  4.7K_0402_5%  [R_0402]  59.8 79.37 0 top
RZ19  4.7K_0402_5%  [R_0402]  59.8 81.15 0 top
RZ20  4.7K_0402_5%  [R_0402]  47.81 75.51 270 top
RZ21  4.7K_0402_5%  [R_0402]  47.81 72.82 90 top
RZ75  0_0402_5%  [R_0402]  143.72 118.43 180 top
RZ79  0_0402_5%  [R_0402]  182.54 117.28 0 bottom
RZ1701  22.1K_0402_1%  [R_0402]  136.35 110.64 270 top
RZ1702  49.9K_0402_1%  [R_0402]  141.17 116.71 180 top
SPK1  E&T_3703-Q04N-11R  [E-T_3703-Q04N-11R_4P]  77.97 5.57 90 bottom
SPR1  SPRING-31-GP  [EMIST_SQ-55G_1P]  66.05 22.72 270 bottom
SPR2  SPRING-24-GP-U  [EMIST-SQ-26G_1P]  75.21 80.36 180 bottom
SPR3  SPRING-13-GP-U  [EMIST_SQ-55G_1P]  160.2 30.8 0 bottom
SW1  TST71-N-220-T170-S017_2P  [SW_TST71-N-220-T170-S017_2P]  201.72 64.3 180 top
T1  PAD~D  [TPC12]  112.19 93.29 0 top
T2  PAD~D  [TPC12]  110.97 94.06 0 top
T3  PAD~D  [TPC12]  105.34 71.06 180 bottom
T4  PAD~D  [TPC12]  104.12 70.35 180 bottom
T5  PAD~D  [TPC12]  107.46 79.81 0 top
T6  PAD~D  [TPC12]  107.46 78.45 0 top
T9  PAD~D  [TPC12]  89.99 96.34 180 bottom
T10  PAD~D  [TPC12]  107.79 98.44 180 bottom
T11  PAD~D  [TPC12]  106.34 98.51 180 bottom
T12  PAD~D  [TPC12]  94.94 72.71 180 bottom
T13  PAD~D  [TPC12]  94.29 73.83 180 bottom
T14  PAD~D  [TPC12]  131.31 82.42 0 top
T15  PAD~D  [TPC12]  132.14 80.52 0 top
T16  PAD~D  [TPC12]  91.66 75.84 180 bottom
T17  PAD~D  [TPC12]  90.3 75.97 180 bottom
T21  PAD  [TPC12]  96.7 98.81 0 top
T22  PAD  [TPC12]  89.93 97.69 180 bottom
T23  PAD  [TPC12]  102.8 94.11 0 top
T24  PAD  [TPC12]  94.96 99.41 0 top
T25  PAD  [TPC12]  96.33 95.65 0 top
T26  PAD  [TPC12]  99.84 95.31 0 top
T27  PAD  [TPC12]  97.78 94.9 0 top
T28  PAD  [TPC12]  94.36 96.39 0 top
T29  PAD  [TPC12]  101.66 92.96 0 top
T30  PAD  [TPC12]  103.69 92.96 0 top
T31  PAD  [TPC12]  89.95 94.93 180 bottom
T32  PAD  [TPC12]  90.63 92.31 180 bottom
T33  PAD  [TPC12]  94.61 95.05 0 top
T34  PAD  [TPC12]  89.97 93.6 180 bottom
T35  PAD  [TPC12]  93.84 92.5 180 bottom
T36  PAD  [TPC12]  89.05 92.31 180 bottom
T37  PAD  [TPC12]  92.2 92.31 180 bottom
T38  PAD  [TPC12]  93.47 94.06 180 bottom
T39  PAD  [TPC12]  99.87 93.22 0 top
T40  PAD  [TPC12]  100.77 94.4 0 top
T41  PAD  [TPC12]  103.7 98.84 0 top
T42  PAD  [TPC12]  103.98 99.95 180 bottom
T43  PAD  [TPC12]  107.39 102.27 180 bottom
T44  PAD  [TPC12]  104.96 99.82 0 top
T45  PAD  [TPC12]  103.69 100.14 0 top
T46  PAD  [TPC12]  102.39 98.54 0 top
T47  PAD  [TPC12]  133.34 99.57 180 bottom
T48  PAD  [TPC12]  154.91 73.62 180 bottom
T49  PAD  [TPC12]  153.42 54.58 180 bottom
T50  PAD  [TPC12]  103.86 98.45 180 bottom
T51  PAD  [TPC12]  105.39 100.36 180 bottom
T52  PAD  [TPC12]  90.61 98.93 180 bottom
T53  PAD  [TPC12]  139.5 88.02 0 top
T86  PAD  [TPC12]  175.57 128.93 180 bottom
T113  PAD~D  [TPC12]  92.49 76.89 180 bottom
T114  PAD~D  [TPC12]  91.1 77.03 180 bottom
T115  PAD~D  [TPC12]  132.12 76.48 0 top
T122  PAD~D  [TPC12]  120.98 92 0 top
T123  PAD~D  [TPC12]  119.74 81.97 0 top
T126  PAD~D  [TPC12]  141.34 75.03 180 bottom
T127  PAD~D  [TPC12]  142.7 75.03 180 bottom
T128  PAD~D  [TPC12]  141.28 79.69 180 bottom
T129  PAD~D  [TPC12]  139.97 79.68 180 bottom
T130  PAD~D  [TPC12]  141.33 73.66 180 bottom
T201  -  [TPC12]  167.7 131.37 0 top
T202  -  [TPC12]  168.64 132.28 0 top
T203  -  [TPC12]  162.74 124.31 0 top
T204  -  [TPC12]  163.89 128.37 0 top
T205  -  [TPC12]  164.73 124.51 0 top
T206  -  [TPC12]  160.92 126.09 0 top
T207  -  [TPC12]  162.74 126.72 0 top
T208  -  [TPC12]  165.84 123.88 0 top
T209  -  [TPC12]  162.06 125.45 0 top
T210  -  [TPC12]  166.6 122.83 0 top
T211  -  [TPC12]  164.14 126.62 0 top
T212  -  [TPC12]  163.79 125.37 0 top
T213  -  [TPC12]  165.16 125.81 0 top
T214  -  [TPC12]  166.81 119.56 180 bottom
T215  -  [TPC12]  166.93 120.9 180 bottom
T216  -  [TPC12]  167.32 127.48 0 top
T217  -  [TPC12]  166.22 126.72 0 top
T218  -  [TPC12]  159.19 130.68 0 top
T221  -  [TPC12]  168.71 122.68 180 bottom
T222  -  [TPC12]  169.35 123.9 180 bottom
T223  -  [TPC12]  171.74 126.54 180 bottom
T224  -  [TPC12]  171.25 125.07 180 bottom
T4931  PAD  [TPC12]  191.06 73.28 180 bottom
T4932  PAD  [TPC12]  186.94 87.69 180 bottom
T4935  -  [TPC12]  158.25 120.27 180 bottom
T4937  PAD~D  [TPC12]  129.99 79.31 0 top
T4938  PAD~D  [TPC12]  156.27 54.1 90 top
T4941  PAD~D  [TPC12]  107.87 99.76 180 bottom
T4942  PAD~D  [TPC12]  106.53 99.78 180 bottom
T4943  PAD~D  [TPC12]  114.9 93.37 0 top
T4944  PAD~D  [TPC12]  113.96 94.23 0 top
T4945  PAD~D  [TPC12]  130.21 70.12 180 bottom
T4946  PAD~D  [TPC12]  102.6 98.72 180 bottom
T4947  PAD~D  [TPC12]  123.92 79.13 0 top
T4948  PAD~D  [TPC12]  124.59 80.71 0 top
T4949  PAD~D  [TPC12]  132.89 79.41 0 top
T4950  PAD~D  [TPC12]  132.33 78.21 0 top
T4951  PAD~D  [TPC12]  104.56 84.99 0 top
T4952  PAD~D  [TPC12]  102.74 84.05 0 top
T4953  PAD~D  [TPC12]  103.48 82.07 0 top
T4954  PAD~D  [TPC12]  103.14 80.12 0 top
TC3501  100U_1206_6.3V6M  [C_1206]  21.67 43.53 270 top
THM26  -  [NCT7718W_MSOP8]  155.99 165.37 0 bottom
TP2702  PAD~D  [TPC12]  179.25 14.1 270 top
TP3001  PAD  [TPC12]  51.83 177.26 0 top
TP3002  PAD  [TPC12]  50.86 178.18 180 top
TP3003  PAD  [TPC12]  50.7 174.07 180 top
TP5802  PAD  [TPC12]  172.76 52.07 0 top
TP5803  PAD  [TPC12]  169.22 48.89 0 top
TP5804  PAD  [TPC12]  172.14 53.21 0 top
TPAD1  JXT_FP202DH-008M10M  [JXT_FP202DH-008M10M_8P]  62.52 72.61 90 top
TR3402  HCM1012GH900BP_4P  [INPAQ_HCM1012GH900BP_4P]  22.75 39.78 0 bottom
TR3403  HCM1012GH900BP_4P  [INPAQ_HCM1012GH900BP_4P]  22.8 37.72 0 bottom
TR3404  MCM1012B900F06BP_4P  [INPAQ_MCM1012B900F06BP_4P]  21.34 35.18 0 top
TR3405  MCM1012B900F06BP_4P  [INPAQ_MCM1012B900F06BP_4P]  184.7 40.89 180 bottom
TR3406  MCM1012B900F06BP_4P  [INPAQ_MCM1012B900F06BP_4P]  184.32 37.08 180 bottom
TR5209  MCM1012B900F06BP_4P  [INPAQ_MCM1012B900F06BP_4P]  95.31 162.55 270 bottom
U15  EM5209VF_SON14_2X3  [TPS22966DPUR_SON14_2X3]  143.81 156.79 180 top
U3201  RTS5170-GR_QFN24_4X4  [RTS5170-GR_QFN24_4X4-S1]  14.31 15.33 90 bottom
U3402  -  [L05ESDL5V0NA-4_SLP2510P8-10-9]  19.01 38.65 270 bottom
U3504  -  [SY6288D20AAC_SOT23-5]  25.36 44.23 90 bottom
U3505  -  [SY6288D20AAC_SOT23-5]  199.2 22.41 0 bottom
U5201  -  [EM5203AJ-20_SOT23-5]  82.4 155.98 90 bottom
U5502  RTD2168-CG_QFN32_5X5  [RTD2168-CG_QFN32_5X5-S]  30.5 66.39 270 top
U5504  -  [CAT24C128WI-GT3_SO8]  30.56 49.18 180 bottom
U5601  TPS2001C_MSOP8~D  [TPS2001C_MSOP8]  182.5 41 90 top
U5602  TPS22967DSGR_SON8_2X2  [TPS22965DSGR_SON8_2X2]  192.01 118.23 180 bottom
UC1  SKL-U_BGA1356  [SKL-U_BGA_1356P-T]  138.46 96.68 0 bottom
UC5  W25Q128FVSIQ_SO8  [W25R128FVSIQ_SO8]  161.46 76.99 0 bottom
UC7  -  [SN74AHC1G08DCKR_SC70-5]  147.82 82.69 270 top
UC14  -  [74AUP1G07GW_TSSOP5]  75.99 70.94 0 bottom
UC15  -  [SN74AHC1G08DCKR_SC70-5]  143.71 117.18 180 top
UC16  -  [74AUP1G07GW_TSSOP5]  163.5 70.63 270 top
UC17  -  [74AUP1G07GW_TSSOP5]  168.67 91.23 270 top
UE1  -  [MEC1404-NU-TR_VTQFP128_14X14]  193.17 68.77 180 top
UE6  -  [SN74LVC1G06DCKR_SC70-5]  180.8 73.52 90 bottom
USB1  LOTES_AUSB0162-P001A~D  [J-L_TNBNRAC70049009_9P]  14.82 43.47 90 bottom
UV1  2160856030-A0_FCBGA631  [216-0842024-A11-MAR_FCBGA_631P]  177.48 134.49 135 bottom
UV2  MC74VHC1G08DFT2G_SC70-5  [SN74AHC1G08DCKR_SC70-5]  139.37 128.08 90 bottom
UV11  -  [ADM1032ARMZ_MSOP8]  181.67 122.3 90 top
UV17  H5TC4G63CFR-N0C FBGA  [H5TC4G63AFR-11C_FBGA_96P]  168.18 162.74 315 bottom
UV18  H5TC4G63CFR-N0C FBGA  [H5TC4G63AFR-11C_FBGA_96P]  172.7 158.21 135 top
UV19  H5TC4G63CFR-N0C FBGA  [H5TC4G63AFR-11C_FBGA_96P]  181.64 149.28 315 bottom
UV20  H5TC4G63CFR-N0C FBGA  [H5TC4G63AFR-11C_FBGA_96P]  186.16 144.75 135 top
UZ2  EM5209VF_SON14_2X3  [TPS22966DPUR_SON14_2X3]  46.98 20.58 180 top
UZ6  -  [SN74AHC1G08DCKR_SC70-5]  180.84 70.98 90 bottom
UZ19  -  [TPS22961DNYR_WSON8]  139.12 113.58 90 top
UZ21  TPS22967DSGR_SON8_2X2  [TPS22965DSGR_SON8_2X2]  134.11 108.22 90 top
WLAN1  LCN_DAN05-67406-0100  [LCN_DAN05-67406-0100_67P]  163.37 63.02 270 bottom
X3001  25MHZ_10PF_5YEA25000102IF50Q3  [Y_5YEA25000102IF50Q3_4P]  49.57 176.84 180 top
XF3101  MHPC_NS681677  [MHPC_NS681677_12P]  28.89 174.82 270 bottom
XF3102  MHPC_NS681677  [MHPC_NS681677_12P]  28.89 165.93 90 top
Y1  32.768KHZ_9PF_X1A000141000200  [Y_X1A000141000200_2P]  192.23 63.88 0 top
YC1  24MHZ_12PF_X3G024000DC1H  [Y_X3G024000DC1H_4P]  127.46 107.8 180 bottom
YC2  32.768KHZ_9PF_X1A000141000200  [Y_X1A000141000200_2P]  145.64 79.22 0 bottom
YV1  27MHZ_10PF_7V27000050  [Y_7V27000011_4P]  142.64 133.18 270 bottom

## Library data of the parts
AFTP2502 AFTP2901-AFTP2904 AFTP3302-AFTP3310 AFTP3401 AFTP5501-AFTP5509 AFTP5601 AFTP6101 AFTP6235 AFTP6305-AFTP6307 AFTP6309-AFTP6311 AFTP6313 TP3001-TP3003 TP5802-TP5804 = TPC12: room: POWER BTN
C24 C26 = C_0402: room: 1V8S_1V5S
C343 C349 C6209 = C_0402: room: AUDIO
C983 C987 C6211 = C_0402: room: APU
C2403 CE62-CE64 CE70 CE72-CE76 CE78 CE84-CE86 = C_0402: room: EC
C2503 C2602 C2603 C2605 C2607-C2609 C2612 C2613 C2705 C2707 C2709 C2710 C2717 C2719 C2720 C2723 C2901 C3001-C3003 C3007-C3009 C3011 C3013-C3019 C3021-C3025 C3106 C3201 C3202 C3204-C3206 C3301 C3403 C3404 C3504 C3507 C3508 C3510 C3517 C3518 C5201-C5203 C5206 C5208-C5214 C5401-C5409 C5501 C5503 C5506 C5507 C5509-C5514 C5516-C5520 C5522 C5524-C5530 C5602-C5604 C5606-C5608 C5611 C5612 C5615 C5616 C5801-C5804 C6201 C6202 C6204-C6206 C6214 C6215 EC2601 EC2602 EC2701 EC2708 EC2709 EC2901-EC2908 EC3101-EC3108 EC3201 EC3301-EC3307 EC5206 EC5210 EC5801 EC5802 EC6101-EC6103 EC6105 EC6207 EC6208 EC9701-EC9703 EC9705 EC9706 EC9708-EC9710 EC9712-EC9717 EC9719 EC9720 EC9732 EC9733 EC9735 EC9736 EC9755 EC9756 = C_0402: room: ETY-ROOM
C2601 C2606 C2701-C2704 C2706 C2708 C2711-C2713 C2715 C2716 C2718 C2907 C2908 C3004 C3005 C3010 C3012 C3203 C3302 C5204 C5205 C5207 C5224 C5502 C5504 C5521 C5523 C5805 C5806 C6213 = C_0603: room: ETY-ROOM
C2604 C2611 = C_0603: room: FAN
C3101 TC3501 = C_1206: room: ETY-ROOM
C3303 C3512 C3513 C3515 C5601 C5605 C5609 C5610 = C_0805: room: ETY-ROOM
C5225 C5226 = C_0402: room: LAN
C6216 C6217 CC10 CV6 CV131 CV133 CV182-CV185 CV188 CV196 CV208 CV212 CV224 CV327 CV399 EC9758-EC9760 PC684 PC691-PC694 PC1422-PC1424 = C_0402
CARD1 = T-SOL_156-1001902605_11P: room: ETY-ROOM
CC4 CC5 CC21-CC27 CC58 CC174-CC187 CC194 CC195 CC199 CC202-CC209 CC211-CC218 CC223-CC225 CC248-CC253 CC255-CC257 CC264-CC266 CC270-CC273 CC281 CC288-CC292 CC296-CC299 CC1101 CC1103 CC1801 CZ1701 = C_0402: room: CPU
CC8 CC9 = C_0402: room: SPI ROM
CC210 CC219-CC221 CC226 = C_0805: room: CPU
CC279 CC280 CC293-CC295 CE89 = C_0603: room: CPU
CD1-CD4 CD12 CD16 CD18 CD69 CD74-CD79 CH101 = C_0402: room: DIMMA
CD5-CD10 CD13-CD15 CD17 CD70-CD73 = C_0603: room: DIMMA
CD11 = C_D3: room: DIMMA
CD19-CD22 CD29-CD32 CD34 CD80-CD83 CH100 = C_0402: room: DIMMB
CD23-CD28 CD35 CD84-CD90 = C_0603: room: DIMMB
CD33 = C_EEFSS0D221R: room: DIMMB
CE8 = C_0402: room: SIO
CE12 CE65-CE69 CE71 CE77 CE79 CE81 CE91 = C_0402: room: KBC
CE82 = C_0402: room: FAN
CE87 CE88 = C_0402: room: THERMAL
CMOS1 = SHORTPADS: User Part Number: PART#; room: CPU
CN6301 = CVILU_CF31241D0R4-10-NH_24P: room: ETY-ROOM
CV1-CV5 CV7-CV11 CV15 CV17 CV18 CV20 CV21 CV26 CV28 CV29 CV33-CV35 CV39-CV42 CV46-CV53 CV56-CV60 CV62-CV66 CV71-CV80 CV82 CV85-CV87 CV89 CV90 CV92-CV121 CV124 CV174-CV181 CV304-CV309 CV312 CV313 CVT90 = C_0402: room: VGA
CV16 CV398 CV402 CV403 = C_0603
CV19 CV27 CV30 CV38 CV43-CV45 CV54 CV55 CV61 CV67-CV70 CV81 CV84 CV88 CV91 CV122 CV123 = C_0603: room: VGA
CV143 CV151 CV186 CV187 CV397 CV400 CV401 = C_0201
CV170 CV171 CV220 CV227 = C_0402: room: VRAM_B
CV198 CV210 CV211 CV393 CV396 = C_0402: room: VRAM_A
CV310 CV311 = C_0402: room: LVDS
CV394 = C_0603: room: VRAM_A
CV395 = C_0201: room: VRAM_A
CZ23 CZ44 CZ45 CZ50 = C_0402: room: UZ2
CZ30 CZ31 = C_0402: room: KBTP
CZ34 = C_0402: room: RSMRST
CZ70 CZ78 CZ1703 = C_0402: room: +1.0V_VCCST
CZ82 CZ86 CZ87 CZ1702 = C_0402: room: +1.0V_VCCSTG
D2501 = BAS40C_SOT23-3: room: ETY-ROOM
D2502 D3801 D5203 D5501 D5503 = RB551V-30_SOD323-2: room: ETY-ROOM
D2601 = LRB551V-30T1G_SOD323-2: room: ETY-ROOM
D2701 = BAT54C-7-F_SOT23-3: room: AUDIO
D5201 D5202 = BAT54C-7-F_SOT23-3: room: ETY-ROOM
D5401 = BAW56W_SOT323-3: room: ETY-ROOM
DA6 = PESD5V0U2BT_SOT23-3: room: LVDS
DA13 DA14 = AZ5125-02SPR7G_SOT23-3: room: AUDIO
DB1 JDEG1 = ACES_51522-01001-001_10P: room: ETY-ROOM
DE8 = AZ5125-01HPR7G_SOD523-2: room: SIO
DZ3-DZ5 = RB751S40T1G_SOD523-2: room: CPU
DZ1701 = RB751S40T1G_SOD523-2: room: +1.0V_VCCSTG
DZ1702 DZ1703 = RB751S40T1G_SOD523-2
EC2703-EC2707 R2701 RC216 RC345 RC385 RC392 RC395 RC1106 = R0402_0OHM: room: CPU
ED6101 = AZ5725-01F_DFN2: room: ETY-ROOM
EU3101 EU3102 = TVWDF1004AD0_DFN9: room: ETY-ROOM
EU3403 = AZC199-02SPR7G_SOT23-3: room: ETY-ROOM
EU5602 U3402 = L05ESDL5V0NA-4_SLP2510P8-10-9: room: ETY-ROOM
F5201 F5203 = F_SMD1812P110TF-24: room: ETY-ROOM
F5501 = F_SPR-P110: room: ETY-ROOM
F6201 = F_NANOSMDC050F-13P2-2: room: KB
FAN1 = E-T_3703K-Q03N-11L_3P: room: ETY-ROOM
FAN261 = APL5606AKI-TRG_SO8: room: ETY-ROOM
FD1-FD6 = FIDUCIAL_C40M80: room: ETY-ROOM
G6101 G6102 = SHORTPADS: User Part Number: PART#; room: ETY-ROOM
H1 H6 = H_3P2-G: room: ETY-ROOM
H2-H5 H7 = H_3P0-G: room: ETY-ROOM
H8 = H_4P0N: room: ETY-ROOM
H9 = H_3P0X3P8N: room: ETY-ROOM
HCPU1 HCPU2 = H_3P7: room: ETY-ROOM
HCPU3 = H_3P4: room: ETY-ROOM
HDA27 = ALC3234-CG_MQFN48_6X6-S: room: ETY-ROOM
HDD1 = ACES_51625-01201-001_12P: room: ETY-ROOM
HGPU1-HGPU3 = H_3P3: room: ETY-ROOM
J10 = JUMP_43X39: room: UZ2
J11 J12 = JUMP_43X118: room: ETY-ROOM
JCRT = C-K_80461-5K1-152_15P-T: room: ETY-ROOM
JDIMM1 = DEREN_40-42271-26001RHF_260P-T: room: DIMMA
JDIMM2 = DEREN_40-42261-26001RHF_260P-T: room: DIMMB
JHDMI = C-K_96067-3K28-192-124_19P: room: ETY-ROOM
JWDB1 = CVILU_CI1804M1VRA-NH_4P: room: ETY-ROOM
KB1 = CVILU_CF32301D0R0-NH_30P-T: room: ETY-ROOM
KB_BL1 = E-T_6913K-Y04N-00L_4P: room: ETY-ROOM
L3001 = ZEN_ZADH-252012MES-4R7M_2P: room: ETY-ROOM
L5501-L5503 = MURAT_BLM18BB221SN1D_2P: room: ETY-ROOM
LCD1 = ACES_51540-04001-P01_40P: room: ETY-ROOM
LED1 = LED_12-22A-S2ST3D-C30-2C_3P: room: ETY-ROOM
LOM30 = RTL8106E-CG_QFN32_4X4-S: room: ETY-ROOM
LV2-LV4 LV7 LV8 RV1-RV6 RV8 RV9 RV11-RV13 RV15-RV17 RV20 RV21 RV28 RV29 RV32-RV41 RV58 RV59 RV72 RV77 RV78 RV81-RV84 RV87-RV91 RV146 RV151-RV154 RV160-RV165 RV260 = R_0402: room: VGA
LV6 = MURAT_BLM15BB221SN1D_2P: room: VGA
ODD1 = ACES_51519-02001-P01_20P: room: ETY-ROOM
PBATT1 = SUYIN_200277GR008M270ZR_8P-T: room: ETY-ROOM
PC1-PC4 PC7 PC8 PC14 PC16 = C_0402: room: PWR_SUPPORT
PC100 PC102 PC103 PC113-PC116 PC127 PC128 PC130-PC133 = C_0402: room: 3_5V
PC104-PC110 PC117 PC118 PC120-PC124 = C_0805: room: 3_5V
PC111 PC112 PC119 PC125 PC126 = C_0603: room: 3_5V
PC200-PC203 PC207 PC208 PC210 PC213 PC214 PC230 PC231 = C_0402: room: 1.2V/0.6V
PC204 PC209 PC215-PC220 = C_0603: room: 1.2V/0.6V
PC205 PC206 PC211 PC212 = C_0805: room: 1.2V/0.6V
PC301 PC302 PC304-PC307 PC309 PC320 PC321 = C_0402: room: 1VALW
PC303 = C_0805: room: 1VALW
PC308 PC310-PC313 = C_0603: room: 1VALW
PC501 PC505-PC507 = C_0603: room: 1.8VALW
PC502-PC504 = C_0402: room: 1.8VALW
PC601 PC602 PC605 PC611 PC613 PC614 PC616-PC621 PC624-PC633 PC635-PC647 PC649-PC655 PC659-PC661 PC663 PC666-PC669 PC671 PC674 PC677 PC679-PC683 PC685-PC688 PC695 = C_0402: room: CPU_CORE
PC603 PC604 PC622 PC662 PC670 PC678 = C_0603: room: CPU_CORE
PC606 PC690 = C_25CL33LD: room: CPU_CORE
PC608 PC612 PC656-PC658 PC664 PC665 PC672 PC673 = C_0805: room: CPU_CORE
PC705 PC708 PC711 PC721 PC742 PC744 PC747-PC749 PC751-PC753 PC765 PC768 PC769 PC777 PC779-PC781 PC790 = C_0402: room: CHARGER
PC750 PC757 PC767 = C_0603: room: CHARGER
PC760-PC764 PC766 PC775 PC776 PC778 = C_0805: room: CHARGER
PC801 PC803 PC805 = C_0402: room: 2.5V
PC802 PC804 = C_0805: room: 2.5V
PC836-PC839 = C_5X4P5
PC1001-PC1029 PC1057-PC1061 PC1064-PC1082 PC1129-PC1146 PC1154-PC1156 PC1158 PC1159 PC1161-PC1163 PC1170-PC1184 PC1221-PC1224 = C_0603: room: CPU_CAP
PC1030-PC1056 PC1083-PC1099 PC1125 PC1126 PC1147-PC1153 PC1164 = C_0201: room: CPU_CAP
PC1062 PC1063 PC1101 PC1127 PC1128 = C_5X4P5: room: CPU_CAP
PC1103-PC1105 PC1112-PC1114 = C_0805: room: VGA_CORE
PC1106-PC1108 PC1115-PC1120 PC1122-PC1124 PC1190-PC1193 PC1226-PC1229 PC1232 PC1233 = C_0402: room: VGA_CORE
PC1109-PC1111 PC1121 PC1230 PC1231 = C_0603: room: VGA_CORE
PC1201 PC1202 PC1204 PC1205 PC1209-PC1212 = C_0402: room: 1.0VS_VCCOPC
PC1203 PC1206-PC1208 = C_0603: room: 1.0VS_VCCOPC
PC1401 PC1402 PC1404-PC1407 PC1409 PC1420 PC1421 = C_0402: room: 1.35VGPU
PC1403 = C_0805: room: 1.35VGPU
PC1408 PC1411-PC1414 = C_0603: room: 1.35VGPU
PD2-PD4 = TVNST52302AB0_SOT523-3: room: PWR_SUPPORT
PD5 PD6 = BAV99W_SC70-3: room: PWR_SUPPORT
PD102 = SDMK0340L-7-F_SOD323-2: room: 3_5V
PD704 = LRB715FT1G_SOT323-3: room: CHARGER
PH601-PH605 PR601 PR604 PR605 PR608 PR610-PR613 PR615 PR617 PR618 PR621-PR623 PR626 PR628-PR657 PR662 PR664 PR666 PR668 PR670 PR673 PR675 PR677 PR678 PR680 PR681 = R_0402: room: CPU_CORE
PH1101 PH1102 PR1101 PR1104-PR1106 PR1110-PR1113 PR1115 PR1117 PR1119-PR1121 PR1124 PR1128-PR1137 PR1140 = R_0402: room: VGA_CORE
PJP1-PJP3 = JUMP_43X79-NPM: room: PWR_SUPPORT
PJP13 PJP21 = JUMP_43X118: room: UZ2
PJP15 = JUMP_43X79: room: 1.35V/0.675V
PJP23 = JUMP_43X79: room: UZ3
PJP27 = JUMP_43X39: room: +1.0V_VCCST
PJP32 = JUMP_43X118: room: +1.0V_VCCSTG
PJP102 PJP103 = JUMP_43X118: room: 3_5V
PJP105 PJP106 = JUMP_43X79-NPM: room: 3_5V
PJP200 = JUMP_43X118: room: 1.2V/0.6V
PJP203 PJP206 = JUMP_43X79: room: 1.2V/0.6V
PJP301 = JUMP_43X79: room: 1VALW
PJP302 = JUMP_43X118: room: 1VALW
PJP501 = JUMP_43X79: room: 1.8VALW
PJP502 = JUMP_43X79: room: 1.5V
PJP601 PJP602 = JUMP_43X118-NPM: room: CPU_CORE
PJP603 = JUMP_43X39: room: CPU_CORE
PJP701 = JUMP_43X118-NPM: room: CHARGER
PJP801 PJP802 = JUMP_43X79: room: 2.5V
PJP1101 = JUMP_43X79-NPM: room: VGA_CORE
PJP1201 = JUMP_43X79-NPM: room: 1.0VS_VCCOPC
PJP1202 = JUMP_43X79: room: 1.0VS_VCCOPC
PJP1401 = JUMP_43X79: room: 1.35VGPU
PJP1402 = JUMP_43X118: room: 1.35VGPU
PJPDC1 = ACES_50458-00601-001_6P-T: room: ETY-ROOM
PL1 PL3 PL4 = 5A_Z150_1210_2P: room: PWR_SUPPORT
PL2 = MURAT_BLM15AG102SN1D_2P: room: PWR_SUPPORT
PL100 PL101 = L_7X7X3_M_2P: room: 3_5V
PL102 PL103 = 5A_Z150_1210_2P: room: 3_5V
PL200 = L_7X7X3_M_2P: room: 1.2V/0.6V
PL201 = 5A_Z150_1210_2P-NPM: room: 1.2V/0.6V
PL301 = L_5X5X3_M_2P: room: 1VALW
PL302 = 5A_Z150_1210_2P-NPM: room: 1VALW
PL501 = L_5X5X3_M_2P: room: 1.8VALW
PL601 = L_5X5X3_M: room: CPU_CORE
PL602 PL606 = 5A_Z150_1210_2P: room: CPU_CORE
PL603-PL605 = L_7X7X4_M: room: CPU_CORE
PL700 = L_7X7X3_M_2P: room: CHARGER
PL704 = CYNTE_PCMB042T-1R0MS_2P: room: CHARGER
PL1101 PL1202 = 5A_Z150_1210_2P: room: VGA_CORE
PL1102 PL1103 = L_7X7X4_M: room: VGA_CORE
PL1201 = CYNTE_PCMB062D-R68MS_2P: room: 1.0VS_VCCOPC
PL1401 = CYNTE_PCMB061H-1R0MS_2P: room: 1.35VGPU
PL1402 = 5A_Z150_1210_2P-NPM: room: 1.35VGPU
PQ1 PQ2 = 2N7002DW-T-R7_SOT363-6: room: PWR_SUPPORT
PQ3 = L2N7002WT1G_SC70-3: room: PWR_SUPPORT
PQ5 = RHU002N06_SOT323-3: room: ETY-ROOM
PQ6 = FDV301N_NL_SOT23-3: room: ETY-ROOM
PQ201 = AON7934_DFN3X3A8-10: room: 1.2V/0.6V
PQ601 = AON7934_DFN3X3A8-10: room: CPU_CORE
PQ704 PQ708 = SIS412DN-T1-GE3_POWERPAK8-5: room: CHARGER
PQ709 = L2N7002WT1G_SC70-3: room: CHARGER
PQ710 = LMUN5113T1G_SOT323-3: room: CHARGER
PQ711 = LTC015EUBFS8TL_UMT3F: room: CHARGER
PQ712 = L2N7002WT1G_SC70-3
PQ717 PQ718 PQ740 = SIR472DP-T1-GE3_POWERPAK8-5: room: CHARGER
PQ720 PQ721 = RUM002N02GT2L_VMT3: room: CHARGER
PQ1101-PQ1106 = SIR472DP-T1-GE3_POWERPAK8-5: room: VGA_CORE
PR2 PR7 PR10-PR13 PR15 PR16 PR18 PR20 PR29 PR31-PR33 = R_0402: room: PWR_SUPPORT
PR3 PR4 PR6 PR8 PR9 PR28 R1902 R2405 R2502 R2504 R2603-R2605 R2608-R2610 R2707 R2709 R2711 R2717 R2722 R2908 R2910 R2912 R2913 R2919-R2922 R3015 R3021-R3023 R3032 R3201 R3203-R3205 R5202-R5205 R5207-R5210 R5212 R5218 R5219 R5222 R5401-R5408 R5410-R5419 R5501 R5502 R5505 R5507-R5517 R5602 R5604 R5607 R5801 R5802 R5806 R5810 R6102 R6103 R6107 R6109 R6110 R6201-R6203 R6206 R6207 R6209 R6215 R6301 R6302 R6505 R6507 R6512 R6514 R6517-R6520 RE399 RE400 = R_0402: room: ETY-ROOM
